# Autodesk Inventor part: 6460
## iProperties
Author: Ole Germer
Shininess: 64.0
Angle Display Precision: 2
Document Length Units: 11272
Document Angle Units: 11286
Document Time Units: 11279
Document Mass Units: 11290
Document Length Units Precision: 3
Document Angle Units Precision: 2
Compacted: True
PropertySet Name: _Private Model Information
Created: 2002-10
Part Number: 6460
Material: Stainless Steel, 440C
Document SubType Name: Modeling
Designer: Ole Germer
Control State: 0
Master: False
Checked Out: False
PropertySet Name: Design Tracking Control
Density: 0.0
Volumn: 0.0
Area: 0.0
PropertySet Name: Model Information
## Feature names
1. Revolution1
